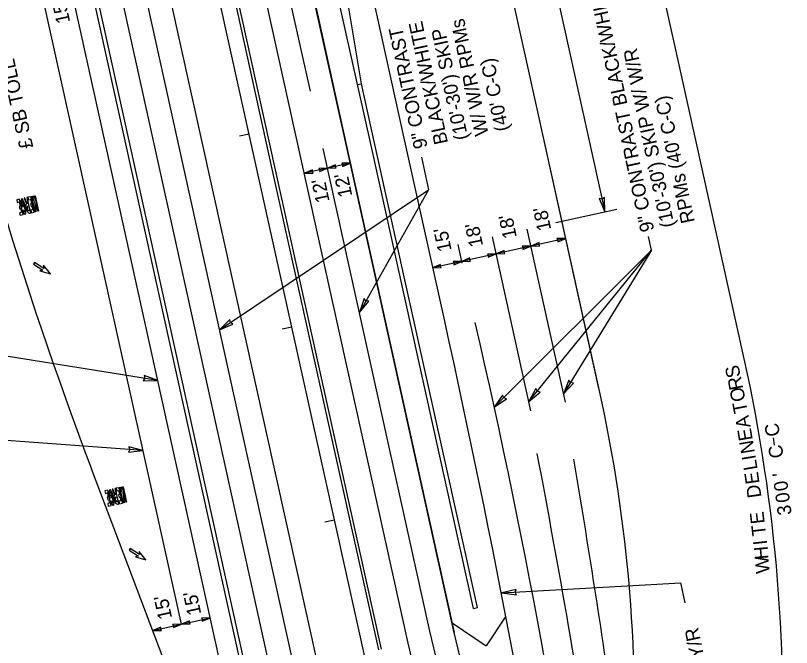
# Model space of a CAD drawing. Extents: x 578088 to 579220, y 1508751 to 1510398.
# Drawn here: x 578348.8 to 578741.3, y 1509588 to 1509907.9 of the extents above; entities that cross this region are included whole.
import ezdxf

# ---------------------------------------------------------------- set-up
doc = ezdxf.new("R2010")
doc.units = 0
for name, color, linetype in [('1', 7, 'Continuous'), ('18', 7, 'Continuous'), ('2', 7, 'Continuous'), ('20', 7, 'Continuous'), ('28', 7, 'Continuous'), ('41', 7, 'Continuous'), ('46', 7, 'Continuous'), ('52', 7, 'Continuous')]:
    doc.layers.add(name, color=color, linetype=linetype)

msp = doc.modelspace()

# ---------------------------------------------------------------- linework, layer by layer
at = {"layer": '1'}
for p, q in [((578639.69, 1509066.69), (578362.17, 1510321.74)), ((578559.88, 1509205.29), (578315.3, 1510311.37))]:
    msp.add_line(p, q, dxfattribs=at)
at = {"layer": '18'}
for p, q in [((578612.63, 1509860.67), (578504, 1510351.92)), ((578545.42, 1509845.81), (578436.79, 1510337.06)), ((578516.77, 1509839.48), (578408.15, 1510330.73)), ((578471.12, 1509495.56), (578291.87, 1510306.19)), ((578415.3, 1510242.58), (578497.77, 1509869.64)), ((578659.48, 1508810.53), (578375.62, 1510094.27)), ((578432.7, 1509599.82), (578361.09, 1509923.69)), ((578643.92, 1509719.15), (578612.63, 1509860.67)), ((578565.9, 1509753.18), (578545.42, 1509845.81)), ((578570.75, 1509595.38), (578516.77, 1509839.48)), ((578627.04, 1509712.12), (578607.66, 1509799.75)), ((578609.54, 1509707.87), (578590.09, 1509795.86)), ((578574.75, 1509782.61), (578572.68, 1509792.01)), ((578569.63, 1509600.44), (578586.86, 1509588.95)), ((578596.83, 1509603.91), (578586.86, 1509588.95)), ((578663.47, 1509155.01), (578558.43, 1509596.29)), ((578617.48, 1509399.06), (578570.71, 1509595.56))]:
    msp.add_line(p, q, dxfattribs=at)
for centre, radius, start, end in [((572971.29, 1508516.11), 5729.75, 9.059044, 12.468543), ((575170.03, 1508961.26), 3501.88, 7.26981, 13.05836), ((577905.47, 1509554.62), 756.56, 356.83788, 12.46827), ((573733.32, 1508756.06), 4967.27, 8.74692, 10.79232), ((573710.87, 1508850.29), 4990.37, 8.10796, 9.60928)]:
    msp.add_arc(centre, radius, start, end, dxfattribs=at)
at = {"layer": '2'}
for p, q in [((578516.94, 1509839.51), (578408.31, 1510330.77)), ((578528.65, 1509842.11), (578420.03, 1510333.36)), ((578493.5, 1509834.33), (578384.88, 1510325.58)), ((578480.88, 1509497.72), (578301.64, 1510308.35)), ((578482.83, 1509498.15), (578303.59, 1510308.78)), ((578523.79, 1509873.37), (578484.67, 1510110.52)), ((578521.84, 1509872.94), (578523.79, 1509873.37)), ((578530.61, 1509842.54), (578523.79, 1509873.37)), ((578570.87, 1509595.6), (578516.94, 1509839.52)), ((578580.47, 1509607.77), (578528.65, 1509842.11)), ((578582.42, 1509608.2), (578530.61, 1509842.54)), ((578547.48, 1509590.23), (578493.5, 1509834.33)), ((578580.47, 1509607.77), (578582.42, 1509608.2)), ((578651.7, 1509152.41), (578547.48, 1509590.23))]:
    msp.add_line(p, q, dxfattribs=at)
at = {"layer": '20'}
for p, q in [((578356.55, 1509816.18), (578355.09, 1509815.86)), ((578358.28, 1509808.37), (578356.55, 1509816.18)), ((578357.03, 1509816.31), (578357.36, 1509816.39)), ((578358.77, 1509808.48), (578357.03, 1509816.31)), ((578357.36, 1509816.39), (578357.87, 1509814.09)), ((578357.69, 1509816.44), (578358.02, 1509816.51)), ((578357.87, 1509814.09), (578357.69, 1509816.44)), ((578358.02, 1509816.51), (578358.85, 1509814.3)), ((578358.34, 1509816.58), (578358.67, 1509816.65)), ((578358.85, 1509814.3), (578358.34, 1509816.58)), ((578360.39, 1509808.84), (578358.67, 1509816.65)), ((578358.67, 1509816.65), (578360.39, 1509808.84)), ((578350.86, 1509814.92), (578349.39, 1509814.6)), ((578349.39, 1509814.6), (578349.68, 1509813.3)), ((578349.68, 1509813.3), (578350.66, 1509813.51)), ((578350.66, 1509813.51), (578351.12, 1509811.4)), ((578352.58, 1509807.11), (578350.86, 1509814.92)), ((578352.09, 1509812.29), (578352.38, 1509812.36)), ((578352.38, 1509812.36), (578352.67, 1509811.06)), ((578353.46, 1509815.5), (578353.13, 1509815.43)), ((578353.13, 1509815.43), (578354.28, 1509812.59)), ((578354.6, 1509812.68), (578353.46, 1509815.5)), ((578354.76, 1509815.79), (578354.44, 1509815.72)), ((578354.44, 1509815.72), (578355.08, 1509812.79)), ((578355.08, 1509812.79), (578354.6, 1509812.68)), ((578356.49, 1509807.98), (578354.76, 1509815.79)), ((578355.09, 1509815.86), (578355.37, 1509814.56)), ((578355.37, 1509814.56), (578356.35, 1509814.77)), ((578356.82, 1509812.66), (578356.33, 1509812.55)), ((578356.33, 1509812.55), (578356.62, 1509811.25)), ((578356.35, 1509814.77), (578356.82, 1509812.66)), ((578360.07, 1509808.77), (578358.47, 1509813.7)), ((578358.47, 1509813.7), (578359.09, 1509808.55)), ((578351.12, 1509811.4), (578350.64, 1509811.29)), ((578350.64, 1509811.29), (578350.92, 1509809.99)), ((578351.81, 1509808.31), (578350.83, 1509808.09)), ((578350.83, 1509808.09), (578351.12, 1509806.79)), ((578350.92, 1509809.99), (578351.41, 1509810.1)), ((578351.41, 1509810.1), (578351.81, 1509808.31)), ((578352.67, 1509811.06), (578352.08, 1509810.93)), ((578352.67, 1509808.56), (578352.71, 1509809.46)), ((578353.94, 1509811.78), (578354.63, 1509808.66)), ((578354.85, 1509811.37), (578355.37, 1509811.48)), ((578355.88, 1509809.21), (578355.33, 1509809.09)), ((578355.37, 1509811.48), (578355.88, 1509809.21)), ((578357.5, 1509809.57), (578356.53, 1509809.35)), ((578356.53, 1509809.35), (578356.81, 1509808.05)), ((578356.62, 1509811.25), (578357.11, 1509811.36)), ((578356.81, 1509808.05), (578358.28, 1509808.37)), ((578357.11, 1509811.36), (578357.5, 1509809.57)), ((578359.09, 1509808.55), (578358.77, 1509808.48)), ((578360.39, 1509808.84), (578360.07, 1509808.77)), ((578351.12, 1509806.79), (578352.58, 1509807.11)), ((578356.16, 1509807.9), (578356.49, 1509807.98)), ((578358.42, 1509782.92), (578357.88, 1509782.07)), ((578357.88, 1509782.07), (578362.59, 1509779.07)), ((578363.13, 1509779.91), (578358.42, 1509782.92)), ((578366.44, 1509777.21), (578362.91, 1509781.44)), ((578362.91, 1509781.44), (578363.13, 1509779.91)), ((578362.59, 1509779.07), (578361.12, 1509778.62)), ((578361.12, 1509778.62), (578366.44, 1509777.21)), ((578395.45, 1509667.66), (578393.99, 1509667.34)), ((578393.99, 1509667.34), (578394.28, 1509666.04)), ((578397.18, 1509659.85), (578395.45, 1509667.66)), ((578398.06, 1509668.24), (578397.73, 1509668.17)), ((578397.73, 1509668.17), (578398.88, 1509665.33)), ((578399.19, 1509665.42), (578398.06, 1509668.24)), ((578399.36, 1509668.53), (578399.04, 1509668.46)), ((578399.04, 1509668.46), (578399.68, 1509665.53)), ((578401.09, 1509660.72), (578399.36, 1509668.53)), ((578401.15, 1509668.92), (578399.69, 1509668.6)), ((578399.69, 1509668.6), (578399.97, 1509667.3)), ((578399.97, 1509667.3), (578400.95, 1509667.51)), ((578400.95, 1509667.51), (578401.42, 1509665.4)), ((578402.88, 1509661.11), (578401.15, 1509668.92)), ((578401.63, 1509669.05), (578401.96, 1509669.13)), ((578403.37, 1509661.22), (578401.63, 1509669.05)), ((578401.96, 1509669.13), (578402.47, 1509666.82)), ((578402.29, 1509669.17), (578402.62, 1509669.25)), ((578402.47, 1509666.82), (578402.29, 1509669.17)), ((578402.62, 1509669.25), (578403.44, 1509667.04)), ((578402.94, 1509669.32), (578403.27, 1509669.39)), ((578403.44, 1509667.04), (578402.94, 1509669.32)), ((578404.99, 1509661.58), (578403.27, 1509669.39)), ((578403.27, 1509669.39), (578404.99, 1509661.58)), ((578394.28, 1509666.04), (578395.25, 1509666.25)), ((578395.72, 1509664.14), (578395.23, 1509664.03)), ((578395.23, 1509664.03), (578395.52, 1509662.73)), ((578395.25, 1509666.25), (578395.72, 1509664.14)), ((578395.52, 1509662.73), (578396.01, 1509662.84)), ((578396.01, 1509662.84), (578396.41, 1509661.05)), ((578396.68, 1509665.03), (578396.98, 1509665.1)), ((578397.27, 1509663.8), (578396.68, 1509663.67)), ((578396.98, 1509665.1), (578397.27, 1509663.8)), ((578398.54, 1509664.52), (578399.23, 1509661.4)), ((578399.68, 1509665.53), (578399.19, 1509665.42)), ((578399.45, 1509664.11), (578399.97, 1509664.22)), ((578399.97, 1509664.22), (578400.47, 1509661.95)), ((578401.42, 1509665.4), (578400.93, 1509665.29)), ((578400.93, 1509665.29), (578401.22, 1509663.99)), ((578401.22, 1509663.99), (578401.71, 1509664.1)), ((578401.71, 1509664.1), (578402.1, 1509662.31)), ((578404.67, 1509661.51), (578403.06, 1509666.44)), ((578403.06, 1509666.44), (578403.69, 1509661.29)), ((578396.41, 1509661.05), (578395.43, 1509660.83)), ((578395.43, 1509660.83), (578395.72, 1509659.53)), ((578395.72, 1509659.53), (578397.18, 1509659.85)), ((578397.27, 1509661.3), (578397.31, 1509662.2)), ((578400.47, 1509661.95), (578399.93, 1509661.82)), ((578400.76, 1509660.64), (578401.09, 1509660.72)), ((578402.1, 1509662.31), (578401.13, 1509662.09)), ((578401.13, 1509662.09), (578401.41, 1509660.79)), ((578401.41, 1509660.79), (578402.88, 1509661.11)), ((578403.69, 1509661.29), (578403.37, 1509661.22)), ((578404.99, 1509661.58), (578404.67, 1509661.51)), ((578406.77, 1509638.17), (578406.23, 1509637.32)), ((578406.23, 1509637.32), (578410.94, 1509634.32)), ((578411.48, 1509635.16), (578406.77, 1509638.17)), ((578414.79, 1509632.46), (578411.26, 1509636.69)), ((578411.26, 1509636.69), (578411.48, 1509635.16)), ((578410.94, 1509634.32), (578409.47, 1509633.88)), ((578409.47, 1509633.88), (578414.79, 1509632.46))]:
    msp.add_line(p, q, dxfattribs=at)
for points in [[(578352.08, 1509810.93), (578351.57, 1509813.25)], [(578351.96, 1509812.88), (578352.09, 1509812.29)], [(578353.6, 1509809.63), (578352.84, 1509813.07)], [(578353.03, 1509813.57), (578353.99, 1509809.26)], [(578396.68, 1509663.67), (578396.17, 1509665.99)], [(578396.56, 1509665.62), (578396.68, 1509665.03)], [(578398.2, 1509662.37), (578397.43, 1509665.81)], [(578397.63, 1509666.31), (578398.59, 1509661.99)]]:
    msp.add_lwpolyline(points, dxfattribs=at)
for centre, major_axis, ratio, start_param, end_param in [((578352.78, 1509811.25), (0.86, -3.91), 0.225, 2.156482, 4.126703), ((578352.78, 1509811.25), (-0.58, 2.6), 0.225, 5.435123, 7.131247), ((578355.59, 1509810.51), (0.58, -2.6), 0.625, 3.662797, 4.068888), ((578352.78, 1509811.25), (0.86, -3.91), 0.225, 5.421015, 7.268296), ((578352.78, 1509811.25), (-0.58, 2.6), 0.225, 2.279423, 3.989655), ((578355.48, 1509810.31), (-0.27, 1.31), 0.625, 0.515234, 2.646405), ((578355.59, 1509810.51), (0.58, -2.6), 0.625, 5.35589, 6.283185), ((578397.38, 1509663.99), (0.86, -3.91), 0.225, 2.156482, 4.126703), ((578397.38, 1509663.99), (-0.58, 2.6), 0.225, 5.435123, 7.131247), ((578400.19, 1509663.25), (0.58, -2.6), 0.625, 3.662797, 4.068888), ((578400.08, 1509663.05), (-0.27, 1.31), 0.625, 0.515234, 2.646405), ((578397.38, 1509663.99), (0.86, -3.91), 0.225, 5.421015, 7.268296), ((578397.38, 1509663.99), (-0.58, 2.6), 0.225, 2.279423, 3.989655), ((578400.19, 1509663.25), (0.58, -2.6), 0.625, 5.35589, 6.283185)]:
    msp.add_ellipse(centre, major_axis=major_axis, ratio=ratio, start_param=start_param, end_param=end_param, dxfattribs=at)
at = {"layer": '28'}
for p, q in [((578466.97, 1509847.82), (578462.08, 1509846.74)), ((578488.56, 1509750.18), (578483.67, 1509749.1)), ((578510.15, 1509652.54), (578505.26, 1509651.46))]:
    msp.add_line(p, q, dxfattribs=at)
at = {"layer": '41'}
for p, q in [((578612.63, 1509860.67), (578504, 1510351.91)), ((578612.63, 1509860.67), (578504, 1510351.91)), ((578612.63, 1509860.67), (578504, 1510351.91)), ((578671.2, 1508813.02), (578338.64, 1510317)), ((578644.18, 1509717.96), (578612.63, 1509860.67)), ((578644.18, 1509717.96), (578612.63, 1509860.67)), ((578644.18, 1509717.96), (578612.63, 1509860.67)), ((578423.98, 1509581.25), (578387.22, 1509678.44))]:
    msp.add_line(p, q, dxfattribs=at)
for centre, radius, start, end in [((580335.96, 1510415.53), 2083.48, 192.46859, 200.71859), ((577905.47, 1509554.62), 756.56, 356.83788, 12.46827), ((577905.47, 1509554.62), 756.56, 356.83788, 12.46827)]:
    msp.add_arc(centre, radius, start, end, dxfattribs=at)
at = {"layer": '46'}
for p, q in [((578371.21, 1510322.56), (578479.83, 1509831.31)), ((578369.74, 1510322.24), (578478.37, 1509830.99)), ((578478.37, 1509830.99), (578532.36, 1509586.8)), ((578479.83, 1509831.31), (578533.83, 1509587.12))]:
    msp.add_line(p, q, dxfattribs=at)
at = {"layer": '52'}
for p, q in [((578612.31, 1509965.1), (578646.95, 1509808.43)), ((578685.86, 1509876.87), (578668.64, 1509954.71)), ((578717.41, 1509734.15), (578685.86, 1509876.87)), ((578558.43, 1509596.29), (578504.42, 1509840.53)), ((578554.13, 1509836.13), (578557.65, 1509819.57)), ((578518.33, 1509833.22), (578506.61, 1509830.63)), ((578510.69, 1509832.36), (578506.61, 1509830.63)), ((578510.54, 1509831.5), (578510.69, 1509832.36)), ((578518.33, 1509833.22), (578513.9, 1509833.1)), ((578513.9, 1509833.1), (578514.4, 1509832.35)), ((578514.26, 1509831.49), (578518.33, 1509833.22)), ((578514.4, 1509832.35), (578514.26, 1509831.49)), ((578506.61, 1509830.63), (578494.9, 1509828.04)), ((578498.97, 1509829.77), (578494.9, 1509828.04)), ((578494.9, 1509828.04), (578499.32, 1509828.16)), ((578498.82, 1509828.91), (578498.97, 1509829.77)), ((578499.32, 1509828.16), (578498.82, 1509828.91)), ((578506.61, 1509830.63), (578502.18, 1509830.51)), ((578502.18, 1509830.51), (578502.69, 1509829.76)), ((578502.54, 1509828.9), (578506.61, 1509830.63)), ((578502.69, 1509829.76), (578502.54, 1509828.9)), ((578506.61, 1509830.63), (578511.04, 1509830.75)), ((578511.04, 1509830.75), (578510.54, 1509831.5)), ((578451.99, 1509748.8), (578557.65, 1509819.57)), ((578557.65, 1509819.57), (578522.75, 1509757.64)), ((578645.56, 1509814.99), (578644.13, 1509815.24)), ((578644.13, 1509815.24), (578646.95, 1509808.43)), ((578646.82, 1509815.82), (578645.56, 1509814.99)), ((578646.95, 1509808.43), (578646.82, 1509815.82)), ((578653.02, 1509809.77), (578622.09, 1509802.94)), ((578627.13, 1509795.06), (578609.56, 1509791.18)), ((578613.63, 1509792.91), (578609.56, 1509791.18)), ((578613.48, 1509792.04), (578613.63, 1509792.91)), ((578627.13, 1509795.06), (578622.7, 1509794.94)), ((578622.7, 1509794.94), (578623.21, 1509794.19)), ((578623.06, 1509793.33), (578627.13, 1509795.06)), ((578623.21, 1509794.19), (578623.06, 1509793.33)), ((578670.54, 1509789.19), (578669.09, 1509795.98)), ((578670.54, 1509789.19), (578591.01, 1509709.67)), ((578609.56, 1509791.18), (578591.98, 1509787.29)), ((578596.06, 1509789.02), (578591.98, 1509787.29)), ((578595.91, 1509788.16), (578596.06, 1509789.02)), ((578609.56, 1509791.18), (578605.13, 1509791.06)), ((578605.13, 1509791.06), (578605.63, 1509790.31)), ((578605.49, 1509789.45), (578609.56, 1509791.18)), ((578605.63, 1509790.31), (578605.49, 1509789.45)), ((578608.5, 1509712.58), (578670.54, 1509789.19)), ((578609.56, 1509791.18), (578613.99, 1509791.29)), ((578613.99, 1509791.29), (578613.48, 1509792.04)), ((578670.54, 1509789.19), (578626.09, 1509716.41)), ((578591.98, 1509787.29), (578574.57, 1509783.44)), ((578578.64, 1509785.17), (578574.57, 1509783.44)), ((578578.5, 1509784.31), (578578.64, 1509785.17)), ((578591.98, 1509787.29), (578587.55, 1509787.17)), ((578587.55, 1509787.17), (578588.06, 1509786.42)), ((578587.91, 1509785.56), (578591.98, 1509787.29)), ((578588.06, 1509786.42), (578587.91, 1509785.56)), ((578591.98, 1509787.29), (578596.41, 1509787.41)), ((578596.41, 1509787.41), (578595.91, 1509788.16)), ((578574.57, 1509783.44), (578559.76, 1509780.16)), ((578563.83, 1509781.9), (578559.76, 1509780.16)), ((578563.69, 1509781.03), (578563.83, 1509781.9)), ((578564.19, 1509780.28), (578563.69, 1509781.03)), ((578574.57, 1509783.44), (578570.14, 1509783.32)), ((578570.14, 1509783.32), (578570.65, 1509782.57)), ((578570.5, 1509781.71), (578574.57, 1509783.44)), ((578570.65, 1509782.57), (578570.5, 1509781.71)), ((578574.57, 1509783.44), (578579, 1509783.56)), ((578579, 1509783.56), (578578.5, 1509784.31)), ((578559.76, 1509780.16), (578564.19, 1509780.28)), ((578525.14, 1509764.62), (578522.75, 1509757.64)), ((578522.75, 1509757.64), (578527.53, 1509763.27)), ((578526.04, 1509763.47), (578525.14, 1509764.62)), ((578527.53, 1509763.27), (578526.04, 1509763.47)), ((578457.26, 1509753.96), (578451.99, 1509748.8)), ((578457.56, 1509752.53), (578457.26, 1509753.96)), ((578451.99, 1509748.8), (578458.79, 1509751.67)), ((578458.79, 1509751.67), (578457.56, 1509752.53)), ((578420.78, 1509723.2), (578314.24, 1509740.29)), ((578420.78, 1509723.2), (578413.85, 1509725.73)), ((578413.85, 1509725.73), (578414.17, 1509724.26)), ((578414.17, 1509724.26), (578413.41, 1509723.01)), ((578413.41, 1509723.01), (578420.78, 1509723.2)), ((578628.72, 1509723.3), (578626.09, 1509716.41)), ((578626.09, 1509716.41), (578631.07, 1509721.86)), ((578629.58, 1509722.12), (578628.72, 1509723.3)), ((578631.07, 1509721.86), (578629.58, 1509722.12)), ((578612.02, 1509719.06), (578608.5, 1509712.58)), ((578612.72, 1509717.79), (578612.02, 1509719.06)), ((578614.15, 1509717.33), (578612.72, 1509717.79)), ((578595.18, 1509715.75), (578591.01, 1509709.67)), ((578595.74, 1509714.4), (578595.18, 1509715.75)), ((578597.12, 1509713.8), (578595.74, 1509714.4)), ((578608.5, 1509712.58), (578614.15, 1509717.33)), ((578591.01, 1509709.67), (578597.12, 1509713.8)), ((578413.27, 1509687.7), (578233.54, 1509701.06)), ((578732.79, 1509690.37), (578732.32, 1509694.12)), ((578406.59, 1509688.19), (578405.94, 1509686.89)), ((578405.94, 1509686.89), (578413.27, 1509687.7)), ((578413.27, 1509687.7), (578406.15, 1509689.63)), ((578406.15, 1509689.63), (578406.59, 1509688.19)), ((578594.88, 1509615.65), (578685.41, 1509620.77)), ((578687.56, 1509610.64), (578685.41, 1509620.77)), ((578602.05, 1509617.41), (578594.88, 1509615.65)), ((578601.57, 1509616.03), (578602.05, 1509617.41)), ((578602.2, 1509614.67), (578601.57, 1509616.03)), ((578594.88, 1509615.65), (578602.2, 1509614.67)), ((578432.7, 1509599.82), (578447.35, 1509603.06)), ((578436.77, 1509601.55), (578432.7, 1509599.82)), ((578436.63, 1509600.69), (578436.77, 1509601.55)), ((578437.13, 1509599.94), (578436.63, 1509600.69)), ((578447.35, 1509603.06), (578442.92, 1509602.94)), ((578442.92, 1509602.94), (578443.42, 1509602.19)), ((578443.28, 1509601.33), (578447.35, 1509603.06)), ((578443.42, 1509602.19), (578443.28, 1509601.33)), ((578418.17, 1509596.6), (578432.7, 1509599.82)), ((578422.24, 1509598.33), (578418.17, 1509596.6)), ((578422.24, 1509598.33), (578418.17, 1509596.6)), ((578418.17, 1509596.6), (578422.6, 1509596.72)), ((578418.17, 1509596.6), (578422.6, 1509596.72)), ((578422.09, 1509597.47), (578422.24, 1509598.33)), ((578422.09, 1509597.47), (578422.24, 1509598.33)), ((578422.6, 1509596.72), (578422.09, 1509597.47)), ((578422.6, 1509596.72), (578422.09, 1509597.47)), ((578432.7, 1509599.82), (578428.27, 1509599.7)), ((578428.27, 1509599.7), (578428.78, 1509598.95)), ((578428.63, 1509598.09), (578432.7, 1509599.82)), ((578428.78, 1509598.95), (578428.63, 1509598.09)), ((578432.7, 1509599.82), (578437.13, 1509599.94))]:
    msp.add_line(p, q, dxfattribs=at)
msp.add_arc((577905.47, 1509554.62), 831.56, 356.83788, 12.46827, dxfattribs=at)

# ---------------------------------------------------------------- texts
for s, rotation, p in [('9" CONTRAST BLACK/WHITE', 102, (578671.97, 1509799.15)), ("15'", 102, (578376.49, 1509904.59)), ('W/ W/R RPMs', 102, (578588.16, 1509847.79)), ('BLACK/WHITE', 102, (578567.62, 1509843.42)), ('9" CONTRAST', 102, (578557.35, 1509841.24)), ("(10'-30') SKIP", 102, (578577.89, 1509845.61)), ("(10'-30') SKIP W/ W/R", 102, (578682.24, 1509801.33)), ('£ SB TOLL', 102.25, (578357.83, 1509841.2)), ("(40' C-C)", 102, (578598.43, 1509849.97)), ("RPMs (40' C-C)", 102, (578692.51, 1509803.51)), ("12'", 102, (578507.73, 1509813.87)), ("12'", 102, (578519.21, 1509816.67)), ("18'", 102, (578619.84, 1509799.62)), ("18'", 102, (578602.43, 1509795.77)), ("18'", 102, (578585.38, 1509791.48)), ("15'", 102, (578569.48, 1509789.1)), ('S', 102.0874, (578715.73, 1509725.31)), ('R', 100.9632, (578717, 1509719.05)), ('O', 100.9632, (578718.15, 1509713.1)), ('T', 100.9632, (578719.27, 1509707.29)), ('A', 100.9632, (578720.74, 1509699.73)), ('E', 99.4763, (578721.78, 1509693.2)), ('C', 99.4763, (578735.61, 1509695.4)), ('N', 99.4763, (578722.86, 1509686.72)), ('C', 99.4763, (578737.45, 1509684.38)), ('I', 99.4763, (578723.41, 1509683.45)), ('L', 99.4763, (578724.27, 1509678.27)), ('E', 97.9894, (578725.21, 1509671.18)), ("'", 97.9894, (578738.78, 1509675.24)), ('0', 97.9894, (578739.84, 1509667.66)), ('D', 97.9894, (578726.19, 1509664.19)), ('0', 97.9894, (578740.66, 1509661.82)), ('3', 96.5025, (578741.43, 1509655.35)), ('E', 96.5025, (578727.84, 1509650.94)), ('T', 96.5025, (578728.53, 1509644.89)), ('I', 96.5025, (578729.06, 1509640.25)), ('H', 95.0157, (578729.77, 1509632.87)), ('W', 95.0157, (578730.39, 1509625.75)), ("15'", 102, (578428.03, 1509603.01)), ("15'", 102, (578442.81, 1509605.08)), ('6" YELLOW W/ Y/R', 102, (578711.15, 1509518))]:
    msp.add_text(s, height=7, rotation=rotation, dxfattribs=at).set_placement(p)

doc.saveas('drawing.dxf')
